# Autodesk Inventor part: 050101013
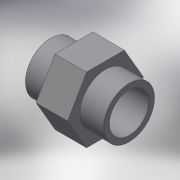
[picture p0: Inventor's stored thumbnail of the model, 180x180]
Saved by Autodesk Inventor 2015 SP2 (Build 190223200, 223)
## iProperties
Created: 2017-10
Part Number: 050101013
Material: Generic
Description: PLASSON THREADED SOCKET PVC 1.1/4"
Document SubType Name: Modeling
Designer: KIM
Density: 1 g/cm^3
Appearance: Default
Author: KIM
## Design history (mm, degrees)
derived "050101.ipt"
feature "Solid1::050101.ipt"
tag "TaggingFeature1"
body "Solid1"
other parameters: "d0" = 52, "d1" = 38.952, "d2" = 51, "d3" = 38.952, "d4" = 35.0568, "d5" = 22, "d6" = 22, "d7" = 50.6376, "d8" = 50.6376, "d10" = 15.4, "d13" = 0, "d14" = 0.38952, "d15" = 16, "G_" = 38.952, "C_" = 51, "B_" = 16, "lt_" = 22, "H_" = 52
